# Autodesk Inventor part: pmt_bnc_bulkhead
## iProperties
Shininess: 64.0
Length Units: 11272
Angle Units: 11279
Time Units: 11290
Mass Units: 11286
Length Display Precision: 3
Angle Display Precision: 2
Compacted: True
Part Number: pmt_bnc_bulkhead
Document SubType Name: Modeling
Created: 2004-05
Designer: John Blackburn
Manufacturer: Standard
Standards Organization: Custom
Density: 0.0
Volumn: 0.0
Area: 0.0
PropertySet Name: Model Information
Control State: 0
Master: False
Checked Out: False
Author: John Blackburn
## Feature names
1. Extrusion1
2. Extrusion2
3. Extrusion3
4. Chamfer1
5. Revolution1
